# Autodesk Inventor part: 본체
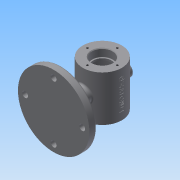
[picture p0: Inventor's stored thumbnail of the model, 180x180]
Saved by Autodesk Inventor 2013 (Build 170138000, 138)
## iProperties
Created: 2018-12
Part Number: 본체
Material: 일반
Document SubType Name: Modeling
Designer: Administrator
Density: 1 g/cm^3
Author: Administrator
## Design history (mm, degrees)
sketch "스케치1"
  geometry: C1 r 30 at (0, 0); 1 further point
  constraints: 1 centre point, 1 coincident
  dimensions: "d0" = 30 radius of C1
extrude "돌출1" new body sketch "스케치1" distance "d1" = 35; taper "d2" = 0 deg
sketch "스케치2"
  geometry: C1 r 16 at (0, 0); 1 further point
  constraints: 1 centre point, 1 coincident
  dimensions: "d3" = 16 radius of C1
extrude "돌출2" cut sketch "스케치2" distance "d4" = 12; taper "d5" = 0 deg
sketch "스케치3"
  geometry: C1 r 14 at (0, 0); 1 further point
  constraints: 1 centre point, 1 coincident
  dimensions: "d6" = 14 radius of C1
extrude "돌출3" cut sketch "스케치3" distance "d7" = 3; taper "d8" = 0 deg
sketch "스케치4"
  geometry: C1 r 25 at (0, 0); 1 further point
  constraints: 1 centre point, 1 coincident
  dimensions: "d9" = 25 radius of C1
extrude "돌출4" cut sketch "스케치4" distance "d10" = 20; taper "d11" = 0 deg
sketch "스케치5"
  geometry: C1 r 16 at (0, 0) reference; 2 further points
  constraints: 1 vertical alignment
  dimensions: "d12" = 23 distance of point (0, 23) point (0, 0)
hole "구멍1" sketch "스케치5" at (0, 23) diameter "d13" = 3.242; stored, may be unused: countersink angle "d17" = 90 deg, drill point angle "d19" = 118 deg; dims "d14" = 8, "d15" = 4, "d16" = 2, "d18" = 10
node "작업 평면1"
sketch "스케치6"
  geometry: C1 r 55 at (0, 0); 1 further point
  constraints: 1 centre point, 1 coincident
  dimensions: "d24" = 55 radius of C1
extrude "돌출5" join sketch "스케치6" distance "d25" = 11; taper "d26" = 0 deg
sketch "스케치7"
  geometry: C1 r 12 at (0, 0); 1 further point
  constraints: 1 centre point, 1 coincident
  dimensions: "d28" = 12 radius of C1
extrude "돌출6" join sketch "스케치7" stored distance "d29" = 11; taper "d30" = 0 deg
sketch "스케치8"
  geometry: C1 r 55 at (0, 0) reference; 2 further points
  constraints: 1 vertical alignment
  dimensions: "d53" = 44 distance of point (0, 44) point (0, 0)
extrude "돌출7" join sketch "스케치8" distance "d31" = 15; taper "d32" = -75 deg
node "작업 평면2"
sketch "스케치9"
  geometry: C1 r 10 at (0, 0); 1 further point
  constraints: 1 centre point, 1 coincident
  dimensions: "d34" = 10 radius of C1
extrude "돌출8" join sketch "스케치9" stored distance "d35" = 15; taper "d36" = 0 deg
hole "구멍2" diameter "d39" = 10; stored, may be unused: countersink angle "d43" = 90 deg, drill point angle "d45" = 118 deg; dims "d37" = 10, "d38" = 10, "d40" = 8, "d41" = 4, "d42" = 2, "d44" = 10
node "작업 평면4"
sketch "스케치11"
  geometry: L1 (30, 35)-(-30, 35) reference; L2 (30, -35)-(30, 35) reference; 2 further points
  constraints: 1 other
  dimensions: "d48" = 35 distance from line of point (0, 0) L1; "d49" = 30 distance from line of point (0, 0) L2
feature "엠보싱1" sketch "스케치11" dims "d50" = 0.5, "d51" = 0
sketch "스케치15"
  geometry: C1 r 4.5 at (0, 44); 1 further point
  constraints: 1 centre point, 1 vertical alignment
  dimensions: "d68" = 9 diameter of C1; "d69" = 44 distance of C1.centre point (0, 0)
extrude "돌출9" cut sketch "스케치15" distance "d70" = 20; taper "d71" = 0 deg
node "작업 평면6"
sketch "스케치16"
  geometry: C1 r 4.5 at (0, 44) reference; C2 r 7 at (0, 44); 1 further point
  constraints: 1 centre point, 1 coincident
  dimensions: "d73" = 14 diameter of C2
extrude "돌출10" cut sketch "스케치16" distance "d74" = 20; taper "d75" = 0 deg
fillet "모깎기1" dims "d79" = 3
fillet "모깎기2" dims "d80" = 3
fillet "모깎기3" dims "d81" = 3
chamfer "모따기1" distance "d82" = 1; stored, may be unused: second distance "d83" = 2, angle "d84" = 45 deg
fillet "모깎기4" dims "d85" = 3
fillet "모깎기5" dims "d86" = 0.3
chamfer "모따기2" distance "d87" = 1; stored, may be unused: second distance "d88" = 2, angle "d89" = 45 deg
node "솔리드1"
mirror "대칭1"
pattern_circular "원형 패턴1" dims angle "d21" = 360 deg
mirror "대칭2"
pattern_circular "원형 패턴2" dims angle "d77" = 360 deg
other parameters: "d23" = -75, "d33" = -112, "d47" = 47
